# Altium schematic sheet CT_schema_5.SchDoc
size 297 x 271 mm
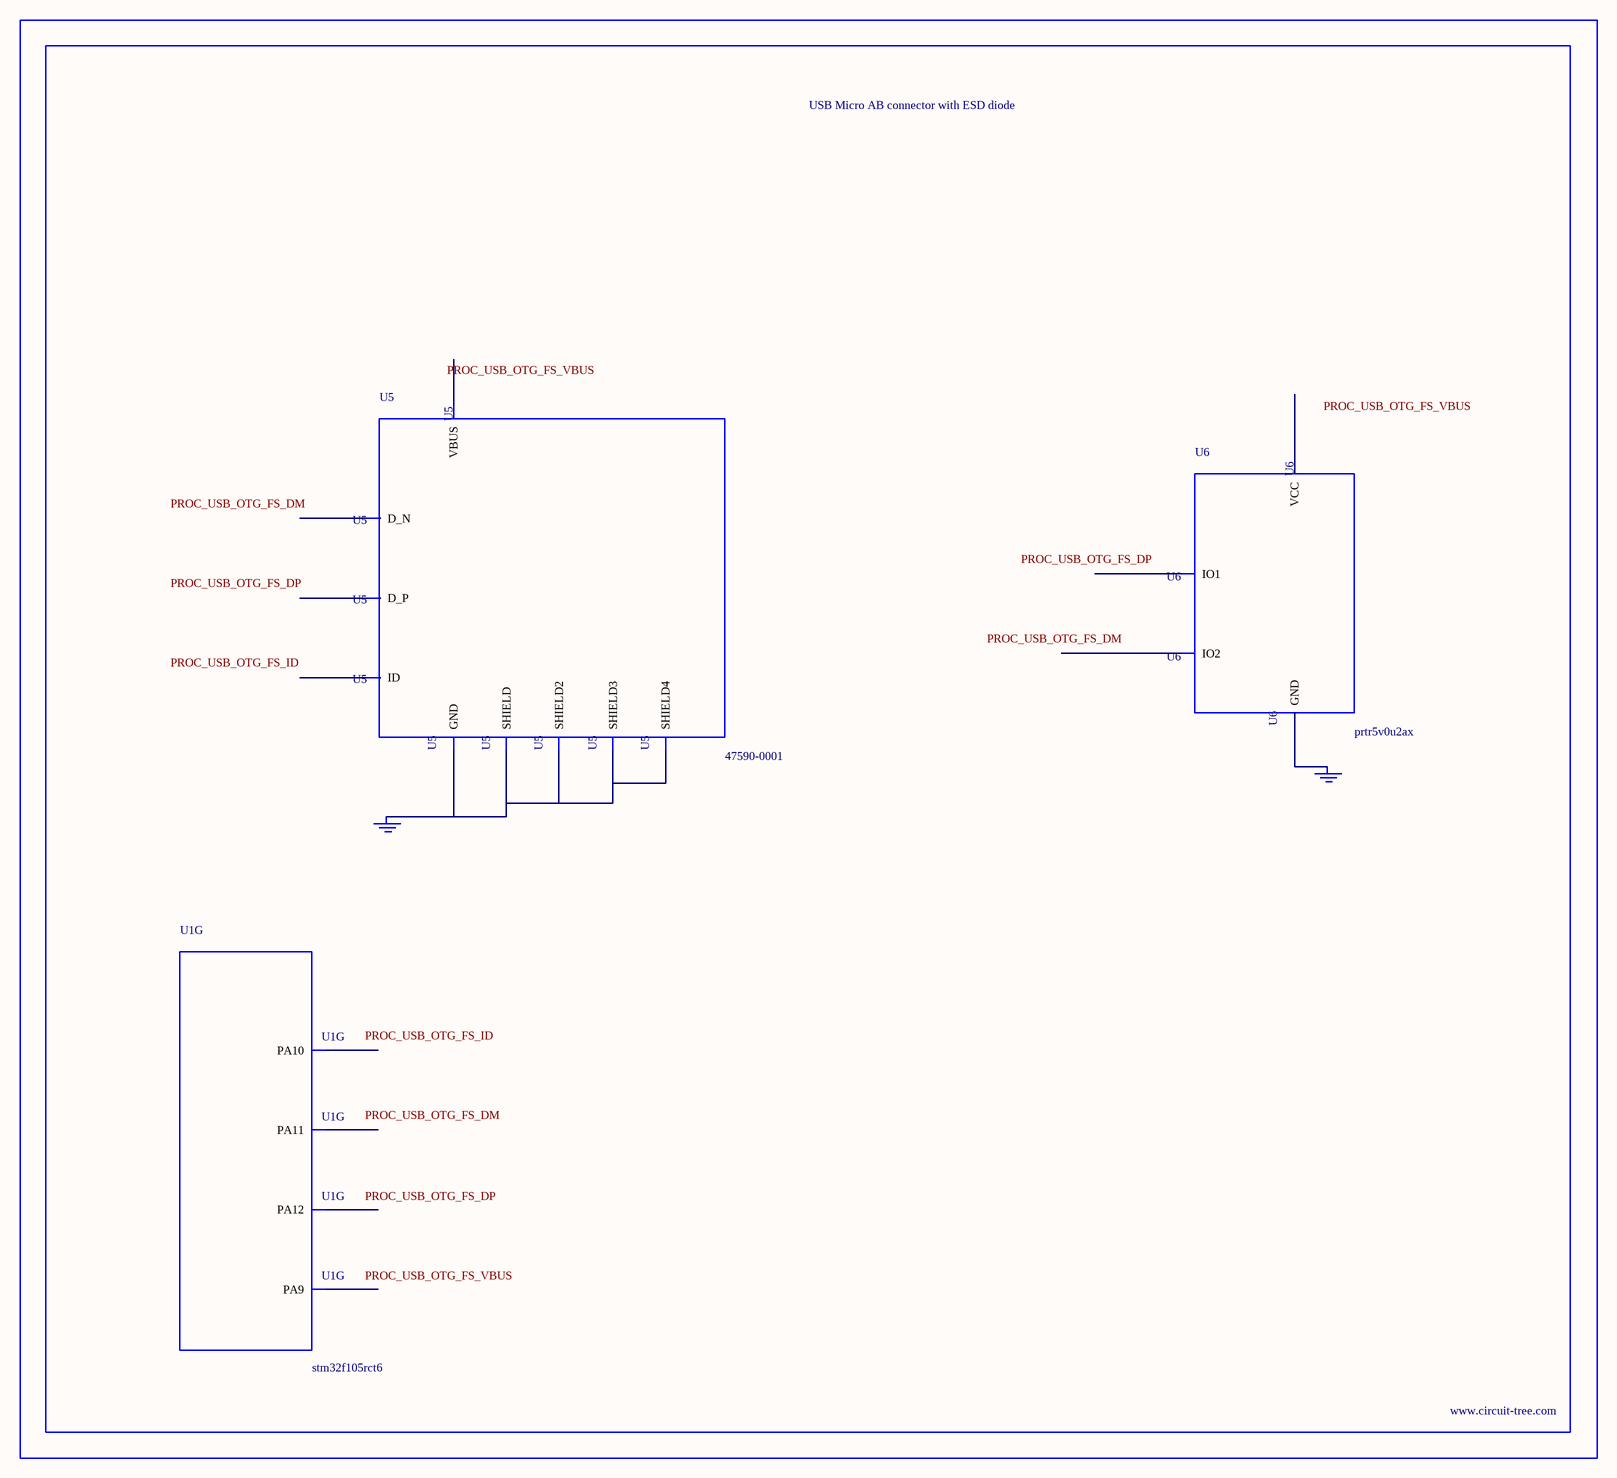
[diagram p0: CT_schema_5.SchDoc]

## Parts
BORDER4  (no value)
GND_INSTANCE_4_0  (no value)
GND_INSTANCE_4_1  (no value)
U1  stm32f105rct6  [LQFP64]  (part G of 7)
U5  47590-0001  [MICRO_USB_AB]
U6  prtr5v0u2ax  [SOT143B]

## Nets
NetGND_INSTANCE_4_0_0: GND_INSTANCE_4_0.0(GND) U5.5(GND) U5.6(SHIELD) U5.7(SHIELD2) U5.8(SHIELD3) U5.9(SHIELD4)
NetGND_INSTANCE_4_1_0: GND_INSTANCE_4_1.0(GND) U6.1(GND)

Not connected (* = marked no-connect by the designer): U1 42(PA9) 43(PA10) 44(PA11) 45(PA12); U5 1(VBUS) 2(D_N) 3(D_P) 4(ID); U6 2(IO1) 3(IO2) 4(VCC)

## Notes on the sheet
- Labels drawn without touching a wire or pin: PROC_USB_OTG_FS_DM, PROC_USB_OTG_FS_DP, PROC_USB_OTG_FS_ID, PROC_USB_OTG_FS_VBUS

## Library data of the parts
BORDER4 = BORDER_PAGE4
GND_INSTANCE_4_0 GND_INSTANCE_4_1 = GND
